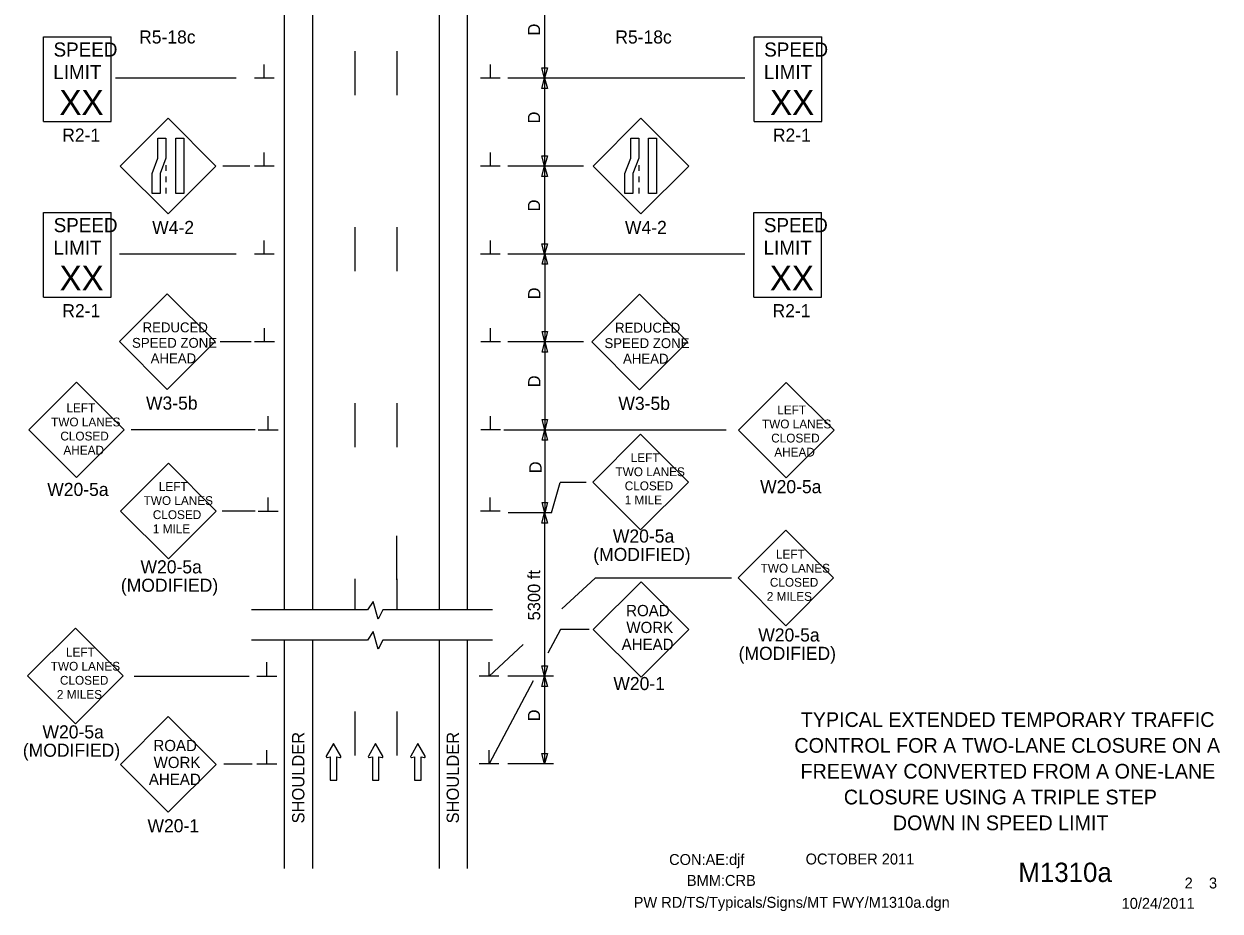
# Model space of a CAD drawing. Extents: x 16724 to 19508, y 5703 to 6974.
# Drawn here: x 17753 to 18433, y 5932 to 6436 of the extents above; entities that cross this region are included whole.
import ezdxf

# ---------------------------------------------------------------- set-up
doc = ezdxf.new("R2010")
doc.units = 0
for name, color, linetype in [('ALI_LEGAL_EX', 7, 'Continuous'), ('BORDER', 7, 'Continuous'), ('BORDER_SIGNAL_WO', 7, 'Continuous'), ('Level 3', 7, 'Continuous'), ('MT_SCRATCH_LEVEL_E', 7, 'Continuous'), ('PAVT_EDGE_EX', 7, 'Continuous'), ('TRAFFIC_SIGNS_PR', 7, 'Continuous'), ('TYPICAL_TEXT_DIMEN_PR', 7, 'Continuous')]:
    doc.layers.add(name, color=color, linetype=linetype)

msp = doc.modelspace()

# ---------------------------------------------------------------- linework, layer by layer
at = {"layer": 'ALI_LEGAL_EX'}
for points in [[(17940.96, 6420.69), (17940.96, 6395.69)], [(17964.96, 6420.69), (17964.96, 6395.69)], [(17940.96, 6320.69), (17940.96, 6295.69)], [(17964.96, 6320.69), (17964.96, 6295.69)], [(17940.96, 6220.69), (17940.96, 6195.69)], [(17964.96, 6220.69), (17964.96, 6195.69)], [(17964.96, 6120.25), (17964.96, 6145.25)], [(17940.96, 6120.69), (17940.96, 6103.04)], [(17964.96, 6120.69), (17964.96, 6103.04)], [(17940.96, 6045.25), (17940.96, 6020.25)], [(17964.96, 6045.25), (17964.96, 6020.25)]]:
    msp.add_lwpolyline(points, dxfattribs=at)
at = {"layer": 'Level 3'}
msp.add_line((18052.76, 6158.34), (18057.75, 6175.43), dxfattribs=at)
at = {"layer": 'MT_SCRATCH_LEVEL_E'}
for p, q in [((17928.96, 6027.15), (17924.85, 6019.91)), ((17933.1, 6019.91), (17928.96, 6027.15)), ((17952.86, 6027.15), (17948.75, 6019.91)), ((17957.01, 6019.91), (17952.86, 6027.15)), ((17976.91, 6027.15), (17972.8, 6019.91)), ((17981.06, 6019.91), (17976.91, 6027.15)), ((17925.33, 6019.23), (17927.1, 6019.54)), ((17927.1, 6019.54), (17927.1, 6006.28)), ((17930.85, 6006.28), (17930.85, 6019.54)), ((17930.85, 6019.54), (17932.62, 6019.23)), ((17949.23, 6019.23), (17951.01, 6019.54)), ((17951.01, 6019.54), (17951.01, 6006.28)), ((17954.75, 6006.28), (17954.75, 6019.54)), ((17954.75, 6019.54), (17956.53, 6019.23)), ((17973.28, 6019.23), (17975.06, 6019.54)), ((17975.06, 6019.54), (17975.06, 6006.28)), ((17978.8, 6006.28), (17978.8, 6019.54)), ((17978.8, 6019.54), (17980.58, 6019.23)), ((17927.1, 6006.28), (17930.85, 6006.28)), ((17951.01, 6006.28), (17954.75, 6006.28)), ((17975.06, 6006.28), (17978.8, 6006.28))]:
    msp.add_line(p, q, dxfattribs=at)
for centre, start, end in [((17925.25, 6019.68), 150.42484, 279.96381), ((17932.69, 6019.68), 260.03619, 29.77312), ((17949.16, 6019.68), 150.42484, 279.96381), ((17956.6, 6019.68), 260.03619, 29.77312), ((17973.21, 6019.68), 150.42484, 279.96381), ((17980.65, 6019.68), 260.03619, 29.77312)]:
    msp.add_arc(centre, 0.463, start, end, dxfattribs=at)
at = {"layer": 'PAVT_EDGE_EX'}
for p, q in [((17900.96, 6925.33), (17900.96, 6103.04)), ((17916.96, 6925.33), (17916.96, 6103.04)), ((17988.96, 6925.33), (17988.96, 6103.04)), ((18004.96, 6925.33), (18004.96, 6103.04)), ((17900.96, 6085.92), (17900.96, 5956.1)), ((17916.96, 6085.92), (17916.96, 5956.1)), ((17988.96, 6085.92), (17988.96, 5956.1)), ((18004.96, 6085.92), (18004.96, 5956.1))]:
    msp.add_line(p, q, dxfattribs=at)
at = {"layer": 'TRAFFIC_SIGNS_PR'}
for p, q in [((17764.03, 6428.82), (17802.48, 6428.82)), ((17764.03, 6380.76), (17764.03, 6428.82)), ((17802.48, 6380.76), (17802.48, 6428.82)), ((18167.98, 6428.82), (18206.43, 6428.82)), ((18167.98, 6380.76), (18167.98, 6428.82)), ((18206.43, 6380.76), (18206.43, 6428.82)), ((17764.03, 6380.76), (17802.48, 6380.76)), ((17834.9, 6382.63), (17807.72, 6355.44)), ((17862.09, 6355.44), (17834.9, 6382.63)), ((18103.65, 6382.63), (18076.46, 6355.44)), ((18130.83, 6355.44), (18103.65, 6382.63)), ((18167.98, 6380.76), (18206.43, 6380.76)), ((17807.72, 6355.44), (17834.9, 6328.25)), ((17833.65, 6355.93), (17833.65, 6352.73)), ((17834.9, 6328.25), (17862.09, 6355.44)), ((18076.46, 6355.44), (18103.65, 6328.25)), ((18102.4, 6355.93), (18102.4, 6352.73)), ((18103.65, 6328.25), (18130.83, 6355.44)), ((17833.65, 6349.52), (17833.65, 6346.32)), ((18102.4, 6349.52), (18102.4, 6346.32)), ((17833.65, 6343.12), (17833.65, 6339.91)), ((18102.4, 6343.12), (18102.4, 6339.91)), ((17764.08, 6328.98), (17802.52, 6328.98)), ((17764.08, 6280.91), (17764.08, 6328.98)), ((17802.52, 6280.91), (17802.52, 6328.98)), ((18167.8, 6328.98), (18206.25, 6328.98)), ((18167.8, 6280.91), (18167.8, 6328.98)), ((18206.25, 6280.91), (18206.25, 6328.98)), ((17834.39, 6282.78), (17807.2, 6255.59)), ((17861.58, 6255.59), (17834.39, 6282.78)), ((17764.08, 6280.91), (17802.52, 6280.91)), ((18102.92, 6282.6), (18075.73, 6255.41)), ((18130.11, 6255.41), (18102.92, 6282.6)), ((18167.8, 6280.91), (18206.25, 6280.91)), ((17807.2, 6255.59), (17834.39, 6228.41)), ((17834.39, 6228.41), (17861.58, 6255.59)), ((18075.73, 6255.41), (18102.92, 6228.23)), ((18102.92, 6228.23), (18130.11, 6255.41)), ((17782.81, 6232.59), (17755.65, 6205.43)), ((17809.96, 6205.43), (17782.81, 6232.59)), ((18186.32, 6232.38), (18159.17, 6205.23)), ((18213.48, 6205.23), (18186.32, 6232.38)), ((17755.65, 6205.43), (17782.81, 6178.28)), ((17782.81, 6178.28), (17809.96, 6205.43)), ((18103.51, 6202.96), (18076.32, 6175.77)), ((18130.69, 6175.77), (18103.51, 6202.96)), ((18159.17, 6205.23), (18186.32, 6178.07)), ((18186.32, 6178.07), (18213.48, 6205.23)), ((17835.06, 6186.49), (17807.87, 6159.3)), ((17862.25, 6159.3), (17835.06, 6186.49)), ((18076.32, 6175.77), (18103.51, 6148.59)), ((18103.51, 6148.59), (18130.69, 6175.77)), ((17807.87, 6159.3), (17835.06, 6132.11)), ((17835.06, 6132.11), (17862.25, 6159.3)), ((18186.06, 6148.46), (18158.87, 6121.27)), ((18213.24, 6121.27), (18186.06, 6148.46)), ((18158.87, 6121.27), (18186.06, 6094.08)), ((18186.06, 6094.08), (18213.24, 6121.27)), ((18103.75, 6119.12), (18076.6, 6091.96)), ((18130.9, 6091.96), (18103.75, 6119.12)), ((17782.19, 6092.71), (17755, 6065.53)), ((17809.38, 6065.53), (17782.19, 6092.71)), ((18076.6, 6091.96), (18103.75, 6064.81)), ((18103.75, 6064.81), (18130.9, 6091.96)), ((17755, 6065.53), (17782.19, 6038.34)), ((17782.19, 6038.34), (17809.38, 6065.53)), ((17835.02, 6042.39), (17807.86, 6015.24)), ((17862.17, 6015.24), (17835.02, 6042.39)), ((17807.86, 6015.24), (17835.02, 5988.09)), ((17835.02, 5988.09), (17862.17, 6015.24))]:
    msp.add_line(p, q, dxfattribs=at)
for points in [[(17833.65, 6371.2), (17833.65, 6360), (17830.31, 6351.11), (17830.31, 6339.91), (17825.81, 6339.91), (17825.81, 6351.11), (17829.16, 6360), (17829.16, 6371.2)], [(17843.8, 6371.2), (17843.8, 6339.91), (17839.3, 6339.91), (17839.3, 6371.2)], [(18102.4, 6371.2), (18102.4, 6360), (18099.05, 6351.11), (18099.05, 6339.91), (18094.55, 6339.91), (18094.55, 6351.11), (18097.9, 6360), (18097.9, 6371.2)], [(18112.55, 6371.2), (18112.55, 6339.91), (18108.05, 6339.91), (18108.05, 6371.2)]]:
    msp.add_lwpolyline(points, close=True, dxfattribs=at)
at = {"layer": 'TYPICAL_TEXT_DIMEN_PR'}
for p, q in [((18048.96, 6455.41), (18048.96, 6405.41)), ((17889.56, 6405.41), (17889.56, 6413.19)), ((18018.08, 6405.41), (18018.08, 6413.19)), ((17873.64, 6405.41), (17805.01, 6405.41)), ((17895.18, 6405.41), (17883.93, 6405.41)), ((18023.71, 6405.41), (18012.46, 6405.41)), ((18070.38, 6405.41), (18027.96, 6405.41)), ((18048.96, 6405.41), (18047.39, 6411.27)), ((18047.39, 6411.27), (18048.96, 6411.27)), ((18047.39, 6399.55), (18048.96, 6405.41)), ((18048.96, 6411.27), (18050.53, 6411.27)), ((18050.53, 6411.27), (18048.96, 6405.41)), ((18048.96, 6405.41), (18048.96, 6355.41)), ((18048.96, 6405.41), (18050.53, 6399.55)), ((18162.77, 6405.41), (18070.38, 6405.41)), ((18048.96, 6399.55), (18047.39, 6399.55)), ((18050.53, 6399.55), (18048.96, 6399.55)), ((17889.56, 6355.41), (17889.56, 6363.19)), ((18018.08, 6355.41), (18018.08, 6363.19)), ((18048.96, 6355.41), (18047.39, 6361.27)), ((18047.39, 6361.27), (18048.96, 6361.27)), ((18048.96, 6361.27), (18050.53, 6361.27)), ((18050.53, 6361.27), (18048.96, 6355.41)), ((17881.37, 6355.41), (17866.01, 6355.41)), ((17895.18, 6355.41), (17883.93, 6355.41)), ((18023.71, 6355.41), (18012.46, 6355.41)), ((18071, 6355.41), (18027.96, 6355.41)), ((18047.39, 6349.55), (18048.96, 6355.41)), ((18048.96, 6355.41), (18048.96, 6305.41)), ((18048.96, 6355.41), (18050.53, 6349.55)), ((18048.96, 6349.55), (18047.39, 6349.55)), ((18050.53, 6349.55), (18048.96, 6349.55)), ((17889.56, 6305.41), (17889.56, 6313.19)), ((18018.08, 6305.41), (18018.08, 6313.19)), ((18048.96, 6305.41), (18047.39, 6311.27)), ((18047.39, 6311.27), (18048.96, 6311.27)), ((18048.96, 6311.27), (18050.53, 6311.27)), ((18050.53, 6311.27), (18048.96, 6305.41)), ((17873.64, 6305.41), (17807.23, 6305.41)), ((17895.18, 6305.41), (17883.93, 6305.41)), ((18023.71, 6305.41), (18012.46, 6305.41)), ((18070.23, 6305.41), (18027.96, 6305.41)), ((18047.52, 6299.55), (18049.09, 6305.41)), ((18049.09, 6305.41), (18049.09, 6255.41)), ((18049.09, 6305.41), (18050.66, 6299.55)), ((18162.77, 6305.41), (18070.23, 6305.41)), ((18049.09, 6299.55), (18047.52, 6299.55)), ((18050.66, 6299.55), (18049.09, 6299.55)), ((17889.69, 6255.41), (17889.69, 6263.19)), ((18018.22, 6255.41), (18018.22, 6263.19)), ((18049.09, 6255.41), (18047.52, 6261.27)), ((18047.52, 6261.27), (18049.09, 6261.27)), ((18049.09, 6261.27), (18050.66, 6261.27)), ((18050.66, 6261.27), (18049.09, 6255.41)), ((17882.14, 6255.41), (17864.57, 6255.41)), ((17895.32, 6255.41), (17884.07, 6255.41)), ((18023.84, 6255.41), (18012.59, 6255.41)), ((18071, 6255.41), (18028.09, 6255.41)), ((18047.52, 6249.55), (18049.09, 6255.41)), ((18049.09, 6249.55), (18047.52, 6249.55)), ((18049.09, 6255.41), (18049.09, 6205.41)), ((18049.09, 6255.41), (18050.66, 6249.55)), ((18050.66, 6249.55), (18049.09, 6249.55)), ((17891.75, 6205.38), (17891.75, 6213.17)), ((18018.22, 6205.41), (18018.22, 6213.19)), ((18049.09, 6205.41), (18047.52, 6211.27)), ((18047.52, 6211.27), (18049.09, 6211.27)), ((18049.09, 6211.27), (18050.66, 6211.27)), ((18050.66, 6211.27), (18049.09, 6205.41)), ((17884.34, 6205.41), (17813.96, 6205.41)), ((17886.13, 6205.38), (17897.38, 6205.38)), ((18023.84, 6205.41), (18012.59, 6205.41)), ((18025.8, 6205.41), (18152.11, 6205.41)), ((18047.52, 6199.55), (18049.09, 6205.41)), ((18049.09, 6205.41), (18049.09, 6158.34)), ((18049.09, 6205.41), (18050.66, 6199.55)), ((18049.09, 6199.55), (18047.52, 6199.55)), ((18050.66, 6199.55), (18049.09, 6199.55)), ((18072.57, 6175.43), (18057.75, 6175.43)), ((17891.75, 6159.28), (17891.75, 6167.07)), ((18018.02, 6159.28), (18018.02, 6167.07)), ((18049.09, 6158.34), (18047.52, 6164.2)), ((18047.52, 6164.2), (18049.09, 6164.2)), ((18049.09, 6164.2), (18050.66, 6164.2)), ((18050.66, 6164.2), (18049.09, 6158.34)), ((17884.34, 6159.28), (17865.73, 6159.28)), ((17886.13, 6159.28), (17897.38, 6159.28)), ((18023.65, 6159.28), (18012.4, 6159.28)), ((18052.76, 6158.34), (18028.16, 6158.34)), ((18047.39, 6152.48), (18048.96, 6158.34)), ((18048.96, 6158.34), (18048.96, 6065.48)), ((18048.96, 6158.34), (18050.53, 6152.48)), ((18048.96, 6152.48), (18047.39, 6152.48)), ((18050.53, 6152.48), (18048.96, 6152.48)), ((18058.7, 6103.65), (18077.58, 6121.06)), ((18155.13, 6121.06), (18077.58, 6121.06)), ((17951.56, 6107.84), (17948.31, 6103.04)), ((17954.3, 6097.9), (17951.56, 6107.84)), ((17948.31, 6103.04), (17882.36, 6103.04)), ((17957.05, 6103.04), (17954.3, 6097.9)), ((18019.38, 6103.04), (17957.05, 6103.04)), ((17948.31, 6085.91), (17882.36, 6085.91)), ((17951.56, 6090.71), (17948.31, 6085.91)), ((17954.3, 6080.77), (17951.56, 6090.71)), ((17957.05, 6085.91), (17954.3, 6080.77)), ((18019.38, 6085.91), (17957.05, 6085.91)), ((18057.94, 6092), (18050.81, 6078.56)), ((18074.23, 6092), (18057.94, 6092)), ((18017.33, 6065.48), (18036.77, 6083.42)), ((17891.07, 6065.48), (17891.07, 6073.27)), ((18017.33, 6065.48), (18017.33, 6073.27)), ((17815.64, 6065.48), (17880.93, 6065.48)), ((17885.44, 6065.48), (17896.69, 6065.48)), ((18022.96, 6065.48), (18011.71, 6065.48)), ((18053.96, 6065.48), (18027.96, 6065.48)), ((18048.96, 6065.48), (18047.39, 6071.34)), ((18047.39, 6071.34), (18048.96, 6071.34)), ((18047.39, 6059.62), (18048.96, 6065.48)), ((18048.96, 6071.34), (18050.53, 6071.34)), ((18050.53, 6071.34), (18048.96, 6065.48)), ((18048.96, 6065.48), (18048.96, 6015.48)), ((18048.96, 6065.48), (18050.53, 6059.62)), ((18042.46, 6062.83), (18017.33, 6015.48)), ((18048.96, 6059.62), (18047.39, 6059.62)), ((18050.53, 6059.62), (18048.96, 6059.62)), ((17891.07, 6015.48), (17891.07, 6023.27)), ((18017.33, 6015.48), (18017.33, 6023.27)), ((18048.96, 6015.48), (18047.39, 6021.34)), ((18047.39, 6021.34), (18048.96, 6021.34)), ((18048.96, 6021.34), (18050.53, 6021.34)), ((18050.53, 6021.34), (18048.96, 6015.48)), ((17866.53, 6015.48), (17882.77, 6015.48)), ((17885.44, 6015.48), (17896.69, 6015.48)), ((18022.96, 6015.48), (18011.71, 6015.48)), ((18053.96, 6015.48), (18027.96, 6015.48))]:
    msp.add_line(p, q, dxfattribs=at)

# ---------------------------------------------------------------- texts
at = {"layer": 'BORDER'}
for s, p in [('TYPICAL EXTENDED TEMPORARY TRAFFIC', (18194.53, 6036.52)), ('CONTROL FOR A TWO-LANE CLOSURE ON A', (18190.9, 6021.85)), ('FREEWAY CONVERTED FROM A ONE-LANE ', (18194.4, 6007.17)), ('CLOSURE USING A TRIPLE STEP', (18219.03, 5992.49)), ('DOWN IN SPEED LIMIT', (18246.9, 5977.82))]:
    msp.add_text(s, height=8.3734, dxfattribs=at).set_placement(p)
at = {"layer": 'BORDER_SIGNAL_WO'}
for s, height, p in [('CON:AE:djf  ', 6.2, (18119.69, 5958.06)), ('    OCTOBER 2011    ', 6.2, (18188.08, 5958.34)), ('    M1310a   ', 11, (18301.86, 5948.38)), ('BMM:CRB   ', 6.2, (18129.81, 5946.17)), (' 2    3 ', 6.2, (18410.45, 5944.7)), ('PW RD/TS/Typicals/Signs/MT FWY/M1310a.dgn      ', 6.2, (18099.55, 5933.71)), ('10/24/2011    ', 6.2, (18376.93, 5933.13))]:
    msp.add_text(s, height=height, dxfattribs=at).set_placement(p)
at = {"layer": 'TRAFFIC_SIGNS_PR'}
for s, height, p in [('R5-18c', 7.44, (17818.45, 6425.09)), ('R5-18c', 7.44, (18089.12, 6425.09)), ('SPEED', 8.01, (17769.8, 6417.67)), ('SPEED', 8.01, (18173.76, 6417.67)), ('LIMIT', 8.01, (17769.64, 6404.86)), ('LIMIT', 8.01, (18173.6, 6404.86)), ('XX', 14.048, (17773.15, 6384.53)), ('XX', 14.048, (18177.11, 6384.53)), ('R2-1', 7.449, (17774.72, 6369.31)), ('R2-1', 7.449, (18178.68, 6369.31)), ('SPEED', 8.01, (17769.85, 6317.82)), ('W4-2', 7.449, (17825.85, 6316.8)), ('W4-2', 7.449, (18094.59, 6316.8)), ('SPEED', 8.01, (18173.58, 6317.82)), ('LIMIT', 8.01, (17769.69, 6305.01)), ('LIMIT', 8.01, (18173.42, 6305.01)), ('XX', 14.048, (17773.2, 6284.68)), ('XX', 14.048, (18176.93, 6284.68)), ('R2-1', 7.449, (17774.77, 6269.46)), ('R2-1', 7.449, (18178.5, 6269.46)), ('REDUCED', 5.607, (17820.43, 6260.91)), ('REDUCED', 5.607, (18088.96, 6260.73)), ('SPEED ZONE', 5.607, (17814.41, 6252.1)), ('SPEED ZONE', 5.607, (18082.94, 6251.92)), ('AHEAD', 5.607, (17824.99, 6243.29)), ('AHEAD', 5.607, (18093.52, 6243.11)), ('W3-5b', 7.449, (17822.33, 6216.95)), ('W3-5b', 7.449, (18090.86, 6216.77)), ('LEFT', 5.006, (17777.12, 6215.42)), ('LEFT', 5.006, (18181.2, 6214.28)), ('TWO LANES', 5.006, (17768.41, 6207.41)), ('TWO LANES', 5.006, (18172.5, 6206.27)), ('CLOSED', 5.006, (17773.66, 6199.4)), ('CLOSED', 5.006, (18177.74, 6198.26)), ('AHEAD', 5.006, (17775.41, 6191.39)), ('AHEAD', 5.006, (18179.49, 6190.25)), ('LEFT', 5.006, (18097.89, 6187.13)), ('TWO LANES', 5.006, (18089.23, 6179.12)), ('W20-5a', 7.44, (17766.22, 6167.86)), ('LEFT', 5.006, (17829.65, 6170.72)), ('CLOSED', 5.006, (18094.47, 6171.11)), ('W20-5a', 7.44, (18171.44, 6169.43)), ('TWO LANES', 5.006, (17821, 6162.72)), ('1 MILE', 5.006, (18094.46, 6163.1)), ('CLOSED', 5.006, (17826.23, 6154.71)), ('1 MILE', 5.006, (17826.23, 6146.7)), ('W20-5a', 7.449, (18087.73, 6141.34)), ('(MODIFIED)', 7.449, (18076.57, 6130.89)), ('LEFT', 5.006, (18180.4, 6132.26)), ('W20-5a', 7.449, (17819.22, 6123.83)), ('TWO LANES', 5.006, (18171.75, 6124.26)), ('(MODIFIED)', 7.449, (17808.06, 6113.38)), ('CLOSED', 5.006, (18176.98, 6116.25)), ('2 MILES', 5.006, (18175.23, 6108.24)), ('ROAD', 6.4, (18095.29, 6099.5)), ('WORK', 6.4, (18095.4, 6089.9)), ('W20-5a', 7.449, (18170.38, 6085.11)), ('AHEAD', 6.4, (18092.71, 6080.3)), ('LEFT', 5.006, (17776.85, 6076.55)), ('(MODIFIED)', 7.449, (18159.22, 6074.66)), ('TWO LANES', 5.006, (17768.2, 6068.54)), ('CLOSED', 5.006, (17773.43, 6060.54)), ('W20-1', 7.44, (18088.02, 6057.49)), ('2 MILES', 5.006, (17771.68, 6052.53)), ('W20-5a', 7.449, (17763.49, 6030.01)), ('(MODIFIED)', 7.449, (17752.33, 6019.56)), ('ROAD', 6.4, (17826.56, 6022.77)), ('WORK', 6.4, (17826.67, 6013.17)), ('AHEAD', 6.4, (17823.98, 6003.57)), ('W20-1', 7.44, (17823.19, 5976.65))]:
    msp.add_text(s, height=height, dxfattribs=at).set_placement(p)
at = {"layer": 'TYPICAL_TEXT_DIMEN_PR'}
for s, p in [('D', (18046.4, 6429.63)), ('D', (18046.4, 6379.63)), ('D', (18046.4, 6329.63)), ('D', (18046.54, 6279.63)), ('D', (18046.54, 6229.63)), ('D', (18047.23, 6180.74)), ('5300 ft', (18046.4, 6097.09)), ('D', (18046.4, 6039.7)), ('SHOULDER', (17912.38, 5981.7)), ('SHOULDER', (18000.24, 5981.7))]:
    msp.add_text(s, height=7, rotation=90, dxfattribs=at).set_placement(p)

doc.saveas('drawing.dxf')
